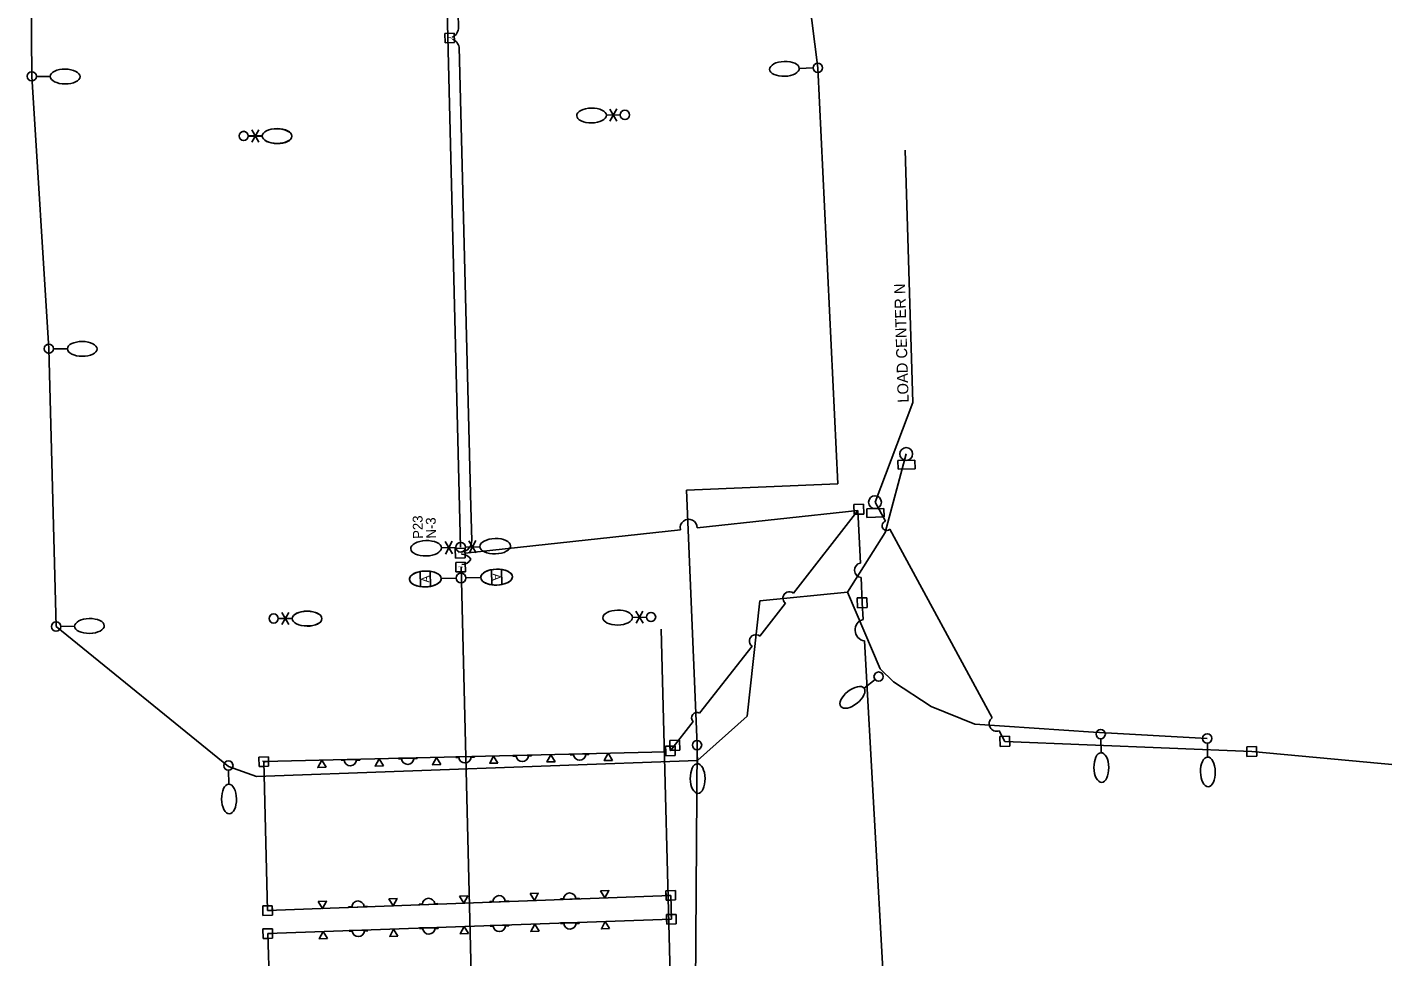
# Model space of a CAD drawing. Extents: x 925407 to 930994, y 604905 to 637063.
# Drawn here: x 929595 to 930286, y 610502 to 610975 of the extents above; entities that cross this region are included whole.
import ezdxf

# ---------------------------------------------------------------- set-up
doc = ezdxf.new("R2010")
doc.units = 0
for name, color, linetype in [('ActivePointCell_dp', 7, 'Continuous'), ('Conduit', 7, 'Continuous'), ('ConduitDB', 7, 'Continuous'), ('ConduitJB', 7, 'Continuous'), ('ConduitOT', 7, 'Continuous'), ('GPKDrCellIns_dp', 7, 'Continuous'), ('LightingMisc', 7, 'Continuous'), ('LiteCond_ep', 7, 'Continuous'), ('LoadCenter', 7, 'Continuous'), ('LoadCenter_ep', 7, 'Continuous'), ('Miscellaneous2', 7, 'Continuous'), ('Miscellaneous9', 7, 'Continuous'), ('PoleLight', 7, 'Continuous'), ('PoleLight_ep', 7, 'Continuous'), ('PullBox', 7, 'Continuous')]:
    doc.layers.add(name, color=color, linetype=linetype)

msp = doc.modelspace()

# ---------------------------------------------------------------- linework, layer by layer
at = {"layer": 'ActivePointCell_dp'}
msp.add_line((930042.23, 610912.84), (930046.23, 610784.25), dxfattribs=at)
msp.add_lwpolyline([(930046.23, 610784.25), (930026.97, 610733.37)], dxfattribs=at)
at = {"layer": 'Conduit'}
for p, q in [((929997.8, 610954.73), (929969.71, 611176.28)), ((929597.01, 610950.4), (929595.71, 611090.79)), ((930007.93, 610742.68), (929997.8, 610954.73)), ((929605.72, 610811.59), (929597.01, 610950.4)), ((929605.72, 610811.59), (929609.4, 610669.96)), ((929930.84, 610739.51), (930007.93, 610742.68)), ((929936.2, 610609.56), (929930.84, 610739.51)), ((929822.99, 610409.48), (929815.93, 610700.2)), ((929961.8, 610624.34), (929968.14, 610683.12)), ((929968.14, 610683.12), (930012.94, 610687.48)), ((930012.94, 610687.48), (930029.62, 610648.47)), ((929609.4, 610669.96), (929697.26, 610598.74)), ((930029.62, 610648.47), (930036.37, 610641.82)), ((930036.37, 610641.82), (930055.61, 610629.26)), ((930055.61, 610629.26), (930077.85, 610620.17)), ((929936.49, 610601.64), (929961.8, 610624.34)), ((930077.85, 610620.17), (930138.42, 610616.12)), ((930138.42, 610616.12), (930196.34, 610612.96)), ((929935.24, 610442.43), (929936.2, 610609.56)), ((929711.58, 610593.62), (929936.49, 610601.64)), ((929697.26, 610598.74), (929711.58, 610593.62))]:
    msp.add_line(p, q, dxfattribs=at)
msp.add_lwpolyline([(930012.94, 610687.48), (930032.16, 610717.96), (930042.85, 610757.95)], dxfattribs=at)
at = {"layer": 'ConduitDB'}
for p, q in [((930018.26, 610729.14), (929936.26, 610720.27)), ((929985.33, 610686.97), (930018.26, 610729.14)), ((929927.69, 610719.34), (929817.94, 610707.47)), ((929968.24, 610665.09), (929981.31, 610681.83)), ((930020.89, 610673.64), (930020.41, 610682.13)), ((930035.34, 610417.86), (930021.51, 610662.68)), ((929937.53, 610625.76), (929964.23, 610659.96)), ((929922.8, 610606.91), (929934.22, 610621.53)), ((930093.16, 610611.48), (930219.02, 610606.34)), ((930219.02, 610606.34), (930335.43, 610595.6))]:
    msp.add_line(p, q, dxfattribs=at)
for centre, radius, start, end in [((929931.92, 610720.35), 4.34, 358.93812, 193.2638), ((929983.26, 610684.45), 3.26, 50.67055, 233.35204), ((930022.39, 610668.23), 5.62, 105.45939, 261.00401), ((929966.17, 610662.58), 3.26, 50.55292, 233.46966), ((929936.12, 610623.45), 2.71, 58.73118, 225.2914)]:
    msp.add_arc(centre, radius, start, end, dxfattribs=at)
at = {"layer": 'ConduitJB'}
for p, q in [((929715.31, 610601.13), (929920.23, 610606.11)), ((929717.26, 610525.22), (929715.31, 610601.13)), ((929717.26, 610525.22), (929922.81, 610533)), ((929923.12, 610520.82), (929922.81, 610533)), ((929717.31, 610513.51), (929923.12, 610520.82)), ((929717.31, 610513.51), (929719.84, 610435.81))]:
    msp.add_line(p, q, dxfattribs=at)
at = {"layer": 'ConduitOT'}
for p, q in [((929814.59, 610975.47), (929814.24, 610989.04)), ((929820.91, 610730.97), (929814.85, 610965.23)), ((929821.35, 610713.85), (929820.91, 610730.97)), ((930026.97, 610733.37), (930032.23, 610723.68)), ((930019.49, 610702.37), (930018.26, 610729.14)), ((930034.48, 610719.54), (930086.64, 610623.49)), ((930020.41, 610682.13), (930019.82, 610695.01)), ((930090.22, 610616.89), (930093.16, 610611.48))]:
    msp.add_line(p, q, dxfattribs=at)
for centre, radius, start, end in [((929809.09, 610975.27), 5.5, 295.12307, 2.09082), ((929809.43, 610964.29), 5.5, 9.84288, 68.44341), ((930032.92, 610721.37), 2.41, 106.59077, 310.41343), ((929815.85, 610713.58), 5.5, 272.68649, 2.83934), ((929816.15, 610701.45), 5.5, 31.59034, 90.26479), ((929816.06, 610707.06), 5.5, 272.68649, 330.23169), ((930020.24, 610698.72), 3.73, 101.70987, 263.53899), ((930088.91, 610620.45), 3.79, 126.74372, 290.26049)]:
    msp.add_arc(centre, radius, start, end, dxfattribs=at)
at = {"layer": 'GPKDrCellIns_dp'}
for p, q in [((929918.49, 610648.7), (929917.98, 610668.7)), ((929918.49, 610648.7), (929917.98, 610668.7)), ((929924.78, 610404.78), (929918.49, 610648.7)), ((929924.78, 610404.78), (929918.49, 610648.7))]:
    msp.add_line(p, q, dxfattribs=at)
at = {"layer": 'LightingMisc'}
for p, q in [((929764.24, 610602.27), (929754.73, 610602.14)), ((929754.73, 610602.14), (929754.73, 610601.83)), ((929754.73, 610601.83), (929756.33, 610601.85)), ((929762.65, 610601.93), (929764.25, 610601.95)), ((929764.25, 610601.95), (929764.24, 610602.27)), ((929793.45, 610602.98), (929783.94, 610602.85)), ((929783.94, 610602.85), (929783.94, 610602.53)), ((929783.94, 610602.53), (929785.54, 610602.56)), ((929791.86, 610602.64), (929793.46, 610602.66)), ((929793.46, 610602.66), (929793.45, 610602.98)), ((929822.67, 610603.69), (929813.15, 610603.56)), ((929813.15, 610603.56), (929813.15, 610603.24)), ((929813.15, 610603.24), (929814.75, 610603.27)), ((929821.07, 610603.35), (929822.67, 610603.37)), ((929822.67, 610603.37), (929822.67, 610603.69)), ((929851.88, 610604.4), (929842.36, 610604.27)), ((929842.36, 610604.27), (929842.36, 610603.95)), ((929842.36, 610603.95), (929843.96, 610603.98)), ((929850.28, 610604.06), (929851.88, 610604.08)), ((929851.88, 610604.08), (929851.88, 610604.4)), ((929881.09, 610605.11), (929871.57, 610604.98)), ((929871.57, 610604.98), (929871.57, 610604.66)), ((929871.57, 610604.66), (929873.18, 610604.68)), ((929879.49, 610604.77), (929881.09, 610604.79)), ((929881.09, 610604.79), (929881.09, 610605.11)), ((929866.51, 610531.23), (929868.12, 610531.27)), ((929866.52, 610530.91), (929866.51, 610531.23)), ((929876.04, 610531.17), (929866.52, 610530.91)), ((929874.43, 610531.44), (929876.03, 610531.49)), ((929876.03, 610531.49), (929876.04, 610531.17)), ((929758.56, 610527.15), (929760.16, 610527.19)), ((929758.57, 610526.83), (929758.56, 610527.15)), ((929768.08, 610527.09), (929758.57, 610526.83)), ((929766.47, 610527.36), (929768.07, 610527.41)), ((929768.07, 610527.41), (929768.08, 610527.09)), ((929794.57, 610528.51), (929796.17, 610528.56)), ((929794.57, 610528.2), (929794.57, 610528.51)), ((929804.09, 610528.45), (929794.57, 610528.2)), ((929802.48, 610528.73), (929804.08, 610528.77)), ((929804.08, 610528.77), (929804.09, 610528.45)), ((929830.54, 610529.88), (929832.14, 610529.92)), ((929830.55, 610529.56), (929830.54, 610529.88)), ((929840.06, 610529.81), (929830.55, 610529.56)), ((929838.45, 610530.09), (929840.06, 610530.13)), ((929840.06, 610530.13), (929840.06, 610529.81)), ((929840.2, 610517.77), (929830.68, 610517.64)), ((929830.68, 610517.64), (929830.68, 610517.32)), ((929830.68, 610517.32), (929832.28, 610517.34)), ((929838.6, 610517.43), (929840.2, 610517.45)), ((929840.2, 610517.45), (929840.2, 610517.77)), ((929876.17, 610519.05), (929866.66, 610518.92)), ((929866.66, 610518.92), (929866.66, 610518.6)), ((929866.66, 610518.6), (929868.26, 610518.62)), ((929874.58, 610518.71), (929876.18, 610518.73)), ((929876.18, 610518.73), (929876.17, 610519.05)), ((929768.27, 610515.22), (929758.76, 610515.09)), ((929758.76, 610515.09), (929758.76, 610514.77)), ((929758.76, 610514.77), (929760.36, 610514.79)), ((929766.68, 610514.88), (929768.28, 610514.9)), ((929768.28, 610514.9), (929768.27, 610515.22)), ((929804.22, 610516.49), (929794.7, 610516.36)), ((929794.7, 610516.36), (929794.7, 610516.05)), ((929794.7, 610516.05), (929796.31, 610516.07)), ((929802.62, 610516.15), (929804.22, 610516.17)), ((929804.22, 610516.17), (929804.22, 610516.49))]:
    msp.add_line(p, q, dxfattribs=at)
for points in [[(929747.08, 610598.25), (929742.86, 610598.15), (929744.88, 610601.85)], [(929776.29, 610598.96), (929772.07, 610598.86), (929774.09, 610602.56)], [(929805.5, 610599.67), (929801.28, 610599.57), (929803.3, 610603.27)], [(929834.71, 610600.38), (929830.49, 610600.28), (929832.51, 610603.98)], [(929863.92, 610601.09), (929859.7, 610600.99), (929861.72, 610604.69)], [(929893.13, 610601.8), (929888.91, 610601.7), (929890.93, 610605.4)], [(929779.08, 610531.21), (929783.3, 610531.37), (929781.33, 610527.64)], [(929815.07, 610532.58), (929819.29, 610532.74), (929817.32, 610529.01)], [(929851.05, 610533.93), (929855.26, 610534.09), (929853.29, 610530.36)], [(929887.02, 610535.29), (929891.24, 610535.45), (929889.27, 610531.72)], [(929743.07, 610529.85), (929747.29, 610530.01), (929745.32, 610526.28)], [(929819.69, 610513.49), (929815.48, 610513.34), (929817.45, 610517.07)], [(929855.67, 610514.77), (929851.46, 610514.61), (929853.43, 610518.34)], [(929891.65, 610516.05), (929887.43, 610515.89), (929889.4, 610519.62)], [(929747.79, 610510.94), (929743.57, 610510.78), (929745.54, 610514.51)], [(929783.73, 610512.22), (929779.52, 610512.06), (929781.49, 610515.79)]]:
    msp.add_lwpolyline(points, close=True, dxfattribs=at)
for centre, start, end in [((929759.48, 610602.21), 186.51447, 355.03606), ((929788.7, 610602.92), 186.51447, 355.03606), ((929817.91, 610603.63), 186.51447, 355.03606), ((929847.12, 610604.34), 186.51447, 355.03606), ((929876.33, 610605.04), 186.51447, 355.03606), ((929799.33, 610528.32), 7.27892, 175.80051), ((929835.31, 610529.69), 7.27892, 175.80051), ((929871.28, 610531.04), 7.27892, 175.80051), ((929763.32, 610526.96), 7.27892, 175.80051), ((929835.44, 610517.7), 186.51447, 355.03606), ((929871.41, 610518.98), 186.51447, 355.03606), ((929763.52, 610515.15), 186.51447, 355.03606), ((929799.46, 610516.43), 186.51447, 355.03606)]:
    msp.add_arc(centre, 3.17, start, end, dxfattribs=at)
at = {"layer": 'LiteCond_ep'}
for p, q in [((929815.68, 610710.4), (929808.33, 611001.71)), ((929922.38, 610609.05), (929920.16, 610608.99)), ((929924.52, 610609.11), (929922.38, 610609.05)), ((929922.44, 610606.9), (929922.38, 610609.05)), ((929922.38, 610609.05), (929922.44, 610606.9)), ((929922.44, 610606.9), (929922.8, 610606.91)), ((929922.8, 610606.91), (929924.52, 610609.11)), ((929924.52, 610609.11), (929922.8, 610606.91)), ((929922.8, 610606.91), (929925.05, 610606.96)), ((929925, 610609.12), (929924.52, 610609.11)), ((929925.05, 610606.96), (929925, 610609.12)), ((929925.12, 610604.27), (929925.05, 610606.96)), ((929717.67, 610603.62), (929712.82, 610603.49)), ((929712.82, 610603.49), (929712.95, 610598.65)), ((929715.31, 610601.13), (929717.73, 610601.19)), ((929717.73, 610601.19), (929715.31, 610601.13)), ((929715.37, 610598.71), (929715.31, 610601.13)), ((929715.31, 610601.13), (929715.37, 610598.71)), ((929717.73, 610601.19), (929717.67, 610603.62)), ((929717.79, 610598.77), (929717.73, 610601.19)), ((929920.28, 610604.15), (929925.12, 610604.27)), ((929712.95, 610598.65), (929715.37, 610598.71)), ((929715.37, 610598.71), (929717.79, 610598.77)), ((929925.17, 610535.48), (929920.32, 610535.36)), ((929920.32, 610535.36), (929920.39, 610532.91)), ((929920.39, 610532.91), (929922.81, 610533)), ((929922.81, 610533), (929920.39, 610532.91)), ((929920.39, 610532.91), (929920.45, 610530.51)), ((929920.45, 610530.51), (929922.87, 610530.58)), ((929922.81, 610533), (929922.87, 610530.58)), ((929922.87, 610530.58), (929922.81, 610533)), ((929922.87, 610530.58), (929925.29, 610530.64)), ((929925.29, 610530.64), (929925.17, 610535.48)), ((929717.2, 610527.64), (929714.77, 610527.58)), ((929714.77, 610527.58), (929714.9, 610522.73)), ((929719.62, 610527.7), (929717.2, 610527.64)), ((929717.26, 610525.22), (929717.2, 610527.64)), ((929717.2, 610527.64), (929717.26, 610525.22)), ((929719.68, 610525.31), (929717.26, 610525.22)), ((929717.26, 610525.22), (929719.68, 610525.31)), ((929719.68, 610525.31), (929719.62, 610527.7)), ((929719.74, 610522.86), (929719.68, 610525.31)), ((929714.9, 610522.73), (929719.74, 610522.86)), ((929923.06, 610523.24), (929920.64, 610523.18)), ((929920.64, 610523.18), (929920.7, 610520.73)), ((929923.12, 610520.82), (929920.7, 610520.73)), ((929920.7, 610520.73), (929923.12, 610520.82)), ((929920.7, 610520.73), (929920.76, 610518.33)), ((929920.76, 610518.33), (929925.6, 610518.46)), ((929925.48, 610523.3), (929923.06, 610523.24)), ((929923.06, 610523.24), (929923.12, 610520.82)), ((929923.12, 610520.82), (929923.06, 610523.24)), ((929925.6, 610518.46), (929925.48, 610523.3)), ((929719.67, 610516), (929714.82, 610515.87)), ((929714.82, 610515.87), (929714.95, 610511.03)), ((929714.95, 610511.03), (929717.39, 610511.09)), ((929717.31, 610513.51), (929719.73, 610513.6)), ((929719.73, 610513.6), (929717.31, 610513.51)), ((929717.39, 610511.09), (929717.31, 610513.51)), ((929717.31, 610513.51), (929717.39, 610511.09)), ((929717.39, 610511.09), (929719.79, 610511.15)), ((929719.73, 610513.6), (929719.67, 610516)), ((929719.79, 610511.15), (929719.73, 610513.6))]:
    msp.add_line(p, q, dxfattribs=at)
for points in [[(929920.16, 610608.99), (929920.23, 610606.11), (929920.28, 610604.15)], [(929925.05, 610606.96), (929922.8, 610606.91), (929922.44, 610606.9)]]:
    msp.add_lwpolyline(points, dxfattribs=at)
at = {"layer": 'LoadCenter'}
for p, q in [((930022.7, 610729.98), (930031.42, 610730.21)), ((930022.81, 610725.62), (930022.7, 610729.98)), ((930031.53, 610725.84), (930022.81, 610725.62)), ((930031.42, 610730.21), (930031.53, 610725.84))]:
    msp.add_line(p, q, dxfattribs=at)
msp.add_circle((930026.97, 610733.37), 3.27, dxfattribs=at)
at = {"layer": 'LoadCenter_ep'}
for p, q in [((930038.57, 610754.56), (930047.29, 610754.79)), ((930038.68, 610750.2), (930038.57, 610754.56)), ((930047.29, 610754.79), (930047.41, 610750.42)), ((930047.41, 610750.42), (930038.68, 610750.2))]:
    msp.add_line(p, q, dxfattribs=at)
msp.add_circle((930042.85, 610757.95), 3.27, dxfattribs=at)
at = {"layer": 'Miscellaneous2'}
for p, q in [((929795.03, 610698.01), (929795.03, 610698.01)), ((929795.03, 610698.01), (929795.23, 610690.34)), ((929800.33, 610690.48), (929800.13, 610698.14)), ((929800.13, 610698.14), (929800.13, 610698.14)), ((929831.37, 610698.94), (929831.37, 610698.94)), ((929831.37, 610698.94), (929831.57, 610691.28)), ((929836.67, 610691.41), (929836.47, 610699.07)), ((929836.47, 610699.07), (929836.47, 610699.07))]:
    msp.add_line(p, q, dxfattribs=at)
for centre, start_param, end_param in [((929797.68, 610694.24), 1.249648, 1.891946), ((929834.02, 610695.18), 1.249648, 1.891946), ((929797.68, 610694.24), 4.391271, 5.033538), ((929797.68, 610694.24), 4.391241, 4.391271), ((929834.02, 610695.18), 4.391271, 5.033538), ((929834.02, 610695.18), 4.391241, 4.391271)]:
    msp.add_ellipse(centre, major_axis=(8.08, 0.21), ratio=0.5, start_param=start_param, end_param=end_param, dxfattribs=at)
at = {"layer": 'PoleLight'}
for p, q in [((929795.23, 610690.34), (929795.03, 610698.01)), ((929800.13, 610698.14), (929800.33, 610690.48)), ((929831.57, 610691.28), (929831.37, 610698.94)), ((929836.47, 610699.07), (929836.67, 610691.41)), ((929813.33, 610694.64), (929805.76, 610694.45)), ((929818.37, 610694.77), (929825.94, 610694.97))]:
    msp.add_line(p, q, dxfattribs=at)
msp.add_circle((929815.85, 610694.71), 2.52, dxfattribs=at)
msp.add_circle((929815.85, 610694.71), 2.52, dxfattribs=at)
for centre in [(929797.68, 610694.24), (929834.02, 610695.18)]:
    msp.add_ellipse(centre, major_axis=(8.08, 0.21), ratio=0.5, dxfattribs=at)
for centre, start_param, end_param in [((929797.68, 610694.24), 1.891945, 4.391241), ((929797.68, 610694.24), 0.847605, 1.249648), ((929797.68, 610694.24), 0, 0.847605), ((929834.02, 610695.18), 1.891945, 4.391241), ((929834.02, 610695.18), 0.847605, 1.249648), ((929834.02, 610695.18), 0, 0.847605), ((929797.68, 610694.24), 5.033538, 6.283185), ((929834.02, 610695.18), 5.033538, 6.283185)]:
    msp.add_ellipse(centre, major_axis=(8.08, 0.21), ratio=0.5, start_param=start_param, end_param=end_param, dxfattribs=at)
at = {"layer": 'PoleLight_ep'}
for p, q in [((929995.43, 610954.66), (929988.34, 610954.44)), ((929599.38, 610950.38), (929606.47, 610950.34)), ((929891.69, 610933.68), (929895.35, 610927.61)), ((929891.8, 610927.54), (929895.24, 610933.75)), ((929897.07, 610930.71), (929889.98, 610930.58)), ((929707.42, 610919.99), (929714.52, 610919.99)), ((929707.42, 610919.98), (929714.52, 610919.94)), ((929712.75, 610923.06), (929709.19, 610916.92)), ((929712.74, 610916.92), (929709.2, 610923.06)), ((929608.09, 610811.58), (929615.18, 610811.54)), ((929813.23, 610710.33), (929805.89, 610710.12)), ((929807.71, 610713.31), (929811.57, 610707.06)), ((929807.89, 610706.95), (929811.38, 610713.42)), ((929818.13, 610710.48), (929825.48, 610710.69)), ((929823.66, 610707.5), (929819.8, 610713.75)), ((929823.47, 610713.86), (929819.99, 610707.39)), ((929728.03, 610677.15), (929724.48, 610671.01)), ((929728.02, 610671.01), (929724.49, 610677.15)), ((929905.01, 610677.78), (929908.66, 610671.7)), ((929905.12, 610671.64), (929908.55, 610677.85)), ((929611.76, 610670), (929618.86, 610670.13)), ((929722.71, 610674.09), (929729.8, 610674.08)), ((929722.71, 610674.07), (929729.81, 610674.03)), ((929910.38, 610674.81), (929903.29, 610674.68)), ((930026.94, 610643), (930021.38, 610638.59)), ((929936.24, 610607.2), (929936.38, 610600.1)), ((930142.05, 610612.81), (930142.18, 610605.71)), ((930196.38, 610610.59), (930196.52, 610603.5)), ((929697.31, 610596.76), (929697.44, 610589.66))]:
    msp.add_line(p, q, dxfattribs=at)
for centre, radius in [((929597.01, 610950.4), 2.37), ((929997.8, 610954.73), 2.37), ((929899.43, 610930.75), 2.36), ((929705.06, 610920), 2.37), ((929705.06, 610920), 2.36), ((929605.72, 610811.59), 2.37), ((929815.68, 610710.4), 2.45), ((929720.34, 610674.09), 2.37), ((929720.34, 610674.09), 2.36), ((929912.75, 610674.85), 2.36), ((929609.4, 610669.96), 2.37), ((930028.79, 610644.47), 2.37), ((930142.01, 610615.17), 2.37), ((930196.34, 610612.96), 2.37), ((929936.2, 610609.56), 2.37), ((929697.26, 610599.12), 2.37)]:
    msp.add_circle(centre, radius, dxfattribs=at)
for centre, major_axis in [((929614.04, 610950.29), (7.57, -0.05)), ((929980.77, 610954.2), (-7.57, -0.24)), ((929882.41, 610930.44), (-7.57, -0.14)), ((929722.08, 610919.98), (7.57, -0.01)), ((929722.09, 610919.89), (7.57, -0.05)), ((929622.75, 610811.49), (7.57, -0.05)), ((929798.05, 610709.88), (-7.84, -0.23)), ((929833.32, 610710.93), (7.84, 0.23)), ((929737.38, 610673.98), (7.57, -0.05)), ((929737.37, 610674.07), (7.57, -0.01)), ((929895.72, 610674.54), (-7.57, -0.14)), ((929626.43, 610670.28), (7.57, 0.14)), ((930015.45, 610633.88), (-5.93, -4.71)), ((929936.52, 610592.53), (0.14, -7.57)), ((930142.33, 610598.14), (0.14, -7.57)), ((930196.66, 610595.93), (0.14, -7.57)), ((929697.59, 610582.09), (0.14, -7.57))]:
    msp.add_ellipse(centre, major_axis=major_axis, ratio=0.5, dxfattribs=at)
at = {"layer": 'PullBox'}
for p, q in [((929807.61, 610972.3), (929812.45, 610972.43)), ((929807.73, 610967.46), (929807.61, 610972.3)), ((929812.58, 610967.58), (929807.73, 610967.46)), ((929812.45, 610972.43), (929812.58, 610967.58)), ((930016.12, 610732.21), (930021.12, 610732.34)), ((930016.25, 610727.21), (930016.12, 610732.21)), ((930021.12, 610732.34), (930021.25, 610727.34)), ((930021.25, 610727.34), (930016.25, 610727.21)), ((929812.88, 610709.84), (929817.87, 610709.97)), ((929813.01, 610704.85), (929812.88, 610709.84)), ((929818, 610704.97), (929813.01, 610704.85)), ((929817.87, 610709.97), (929818, 610704.97)), ((929813.14, 610702.63), (929817.98, 610702.75)), ((929813.26, 610697.79), (929813.14, 610702.63)), ((929818.11, 610697.91), (929813.26, 610697.79)), ((929817.98, 610702.75), (929818.11, 610697.91)), ((930017.85, 610684.57), (930022.85, 610684.7)), ((930017.98, 610679.57), (930017.85, 610684.57)), ((930022.85, 610684.7), (930022.98, 610679.7)), ((930022.98, 610679.7), (930017.98, 610679.57)), ((930090.59, 610613.92), (930095.59, 610614.05)), ((930090.72, 610608.92), (930090.59, 610613.92)), ((930095.59, 610614.05), (930095.72, 610609.05)), ((929920.16, 610608.99), (929925, 610609.12)), ((929920.28, 610604.15), (929920.16, 610608.99)), ((929922.31, 610611.9), (929927.31, 610612.02)), ((929922.44, 610606.9), (929922.31, 610611.9)), ((929927.44, 610607.03), (929922.44, 610606.9)), ((929925, 610609.12), (929925.12, 610604.27)), ((929927.31, 610612.02), (929927.44, 610607.03)), ((930095.72, 610609.05), (930090.72, 610608.92)), ((930216.46, 610608.77), (930221.45, 610608.9)), ((930216.58, 610603.78), (930216.46, 610608.77)), ((930221.45, 610608.9), (930221.58, 610603.91)), ((929712.82, 610603.49), (929717.67, 610603.62)), ((929712.95, 610598.65), (929712.82, 610603.49)), ((929717.67, 610603.62), (929717.79, 610598.77)), ((929925.12, 610604.27), (929920.28, 610604.15)), ((930221.58, 610603.91), (930216.58, 610603.78)), ((929717.79, 610598.77), (929712.95, 610598.65)), ((929920.32, 610535.36), (929925.17, 610535.48)), ((929920.45, 610530.51), (929920.32, 610535.36)), ((929925.29, 610530.64), (929920.45, 610530.51)), ((929925.17, 610535.48), (929925.29, 610530.64)), ((929714.77, 610527.58), (929719.62, 610527.7)), ((929714.9, 610522.73), (929714.77, 610527.58)), ((929719.62, 610527.7), (929719.74, 610522.86)), ((929719.74, 610522.86), (929714.9, 610522.73)), ((929920.64, 610523.18), (929925.48, 610523.3)), ((929920.76, 610518.33), (929920.64, 610523.18)), ((929925.6, 610518.46), (929920.76, 610518.33)), ((929925.48, 610523.3), (929925.6, 610518.46)), ((929714.82, 610515.87), (929719.67, 610516)), ((929714.95, 610511.03), (929714.82, 610515.87)), ((929719.79, 610511.15), (929714.95, 610511.03)), ((929719.67, 610516), (929719.79, 610511.15))]:
    msp.add_line(p, q, dxfattribs=at)

# ---------------------------------------------------------------- texts
at = {"layer": 'ActivePointCell_dp'}
for s, height, rotation, p in [('LOAD CENTER N', 5.6, 91.78324, (930044.13, 610784.18)), ('P23', 5, 91.17666, (929796.44, 610714.74)), ('N-3', 5, 91.17666, (929803.14, 610714.88))]:
    msp.add_text(s, height=height, rotation=rotation, dxfattribs=at).set_placement(p)
at = {"layer": 'Miscellaneous9'}
for rotation, p in [(271.47566, (929831.93, 610697.02)), (91.47566, (929799.77, 610692.39))]:
    msp.add_text('A', height=4.08, rotation=rotation, dxfattribs=at).set_placement(p)
at = {"layer": 'PullBox'}
for height, p in [(1.94, (929811.08, 610969.31)), (2, (929816.46, 610706.76)), (1.94, (929816.61, 610699.64)), (1.94, (929716.29, 610600.5))]:
    msp.add_text('J', height=height, rotation=91.47564, dxfattribs=at).set_placement(p)

doc.saveas('drawing.dxf')
